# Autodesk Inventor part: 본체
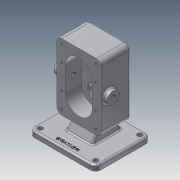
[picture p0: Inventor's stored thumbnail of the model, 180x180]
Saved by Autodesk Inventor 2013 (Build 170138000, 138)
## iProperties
Created: 2020-04
Part Number: 본체
Material: 알루미늄 6061
Document SubType Name: Modeling
Designer: CADCOM
Density: 1 g/cm^3
Author: CADCOM
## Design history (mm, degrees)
sketch "스케치1"
  geometry: L1 (50, 60)-(-50, 60); L2 (-50, 60)-(-50, -60); L3 (-50, -60)-(50, -60); L4 (50, -60)-(50, 60); L5 (50, 60)-(-50, -60); L6 (-50, 60)-(50, -60); 1 further point
  constraints: 12 end point, 2 midpoint, 2 parallel, 1 horizontal, 1 perpendicular
  dimensions: "d0" = 100 distance of L3.end L2.end; "d1" = 120 distance of L2.end L1.end
extrude "돌출1" new body sketch "스케치1" distance "d2" = 10; taper "d3" = 0 deg
fillet "모깎기1" dims "d4" = 10
sketch "스케치2"
  geometry: A1 r 10 centre (-40, -50) between (-50, -50) and (-40, -60) reference; A2 r 10 centre (40, -50) between (40, -60) and (50, -50) reference; A3 r 10 centre (40, 50) between (50, 50) and (40, 60) reference; A4 r 10 centre (-40, 50) between (-40, 60) and (-50, 50) reference; 5 further points
  constraints: 4 coincident
hole "구멍1" sketch "스케치2" at (-40, 50), (40, 50), (40, -50), (-40, -50) diameter "d5" = 9; stored, may be unused: countersink angle "d9" = 90 deg, drill point angle "d11" = 118 deg; dims "d6" = 6, "d7" = 4, "d8" = 2, "d10" = 8
node "작업 평면1"
sketch "스케치3"
  geometry: L1 (20, -40)-(-33, -40); L2 (-33, -40)-(-33, 40); L3 (-33, 40)-(20, 40); L4 (20, 40)-(20, -40); L5 (-40, -60)-(40, -60) reference; L6 (40, 60)-(-40, 60) reference; L7 (-50, 50)-(-50, -50) reference; L8 (20, 0)-(-33, 0); 1 further point
  constraints: 10 end point, 2 midpoint, 2 parallel, 1 horizontal, 1 horizontal alignment, 1 perpendicular
  dimensions: "d13" = 53 distance of L2.end L3.end; "d14" = 80 distance of L1.end L2.end; "d15" = 70 distance between parallel lines of L7 L4
extrude "돌출2" join sketch "스케치3" distance "d16" = 120; taper "d17" = 0 deg
sketch "스케치4"
  geometry: L1 (50, 0)-(-50, 0) reference; L2 (-50, 0)-(-50, 10) reference; L3 (-50, 10)-(50, 10) reference; L4 (50, 10)-(50, 0) reference; L5 (-20, 30)-(-20, 150) reference; L6 (-20, 150)-(33, 150) reference; L7 (33, 150)-(33, 30) reference; L8 (33, 30)-(-20, 30) reference; L9 (21.453, 30)-(33, 10); L10 (-8.453, 30)-(-20, 10); L11 (-8.453, 30)-(21.453, 30); L12 (33, 10)-(-20, 10); 1 further point
  constraints: 8 end point, 4 point on line, 2 collinear
  dimensions: "d18" = 17 distance of L3.end L9.end; "d19" = 60 deg angle of L3 L9; "d20" = 53 distance of L9.end L10.end; "d21" = 60 deg angle of L3 L10
extrude "돌출3" join sketch "스케치4" stored distance "d22" = 48; taper "d23" = 0 deg
fillet "모깎기2" dims "d24" = 9
sketch "스케치5"
  geometry: A1 r 9 centre (0, 9) between (-9, 9) and (0, 0) reference; A2 r 9 centre (62, 9) between (62, 0) and (71, 9) reference; A3 r 9 centre (62, 111) between (71, 111) and (62, 120) reference; A4 r 9 centre (0, 111) between (0, 120) and (-9, 111) reference; 9 further points
  constraints: 4 coincident, 4 vertical alignment, 2 horizontal alignment
  dimensions: "d25" = 29 distance of point (0, 82) point (0, 111); "d27" = 44 distance of point (0, 38) point (0, 82)
hole "구멍2" sketch "스케치5" at (0, 111), (62, 111), (62, 9), (0, 9), (0, 38), (62, 38), (62, 82), (0, 82) diameter "d28" = 4.134; stored, may be unused: countersink angle "d32" = 90 deg, drill point angle "d34" = 118 deg; dims "d29" = 10, "d30" = 4, "d31" = 2, "d33" = 12
sketch "스케치6"
  geometry: L1 (62, 0)-(0, 0) reference; L2 (0, 120)-(62, 120) reference; L3 (-9, 9)-(-9, 111) reference; L4 (7, 82)-(7, 38); L5 (55, 82)-(55, 38); L6 (7, 60)-(55, 60); A1 r 24 centre (31, 38) between (7, 38) and (55, 38); A2 r 24 centre (31, 82) between (55, 82) and (7, 82); 5 further points
  constraints: 6 end point, 6 point on circle, 4 midpoint, 2 centre point, 2 tangent, 2 vertical alignment, 1 parallel
  dimensions: "d36" = 24 radius of A1; "d37" = 92 distance of point (31, 14) point (31, 106); "d38" = 22 distance from line of A2.centre L6; "d39" = 14 distance from line of point (31, 106) L2; "d40" = 24 radius of A2
extrude "돌출4" cut sketch "스케치6" distance "d41" = 29; taper "d42" = 0 deg
sketch "스케치7"
  geometry: C1 r 12.5 at (31, 82); A1 r 24 centre (31, 82) between (55, 82) and (7, 82) reference; 1 further point
  constraints: 1 centre point, 1 coincident
  dimensions: "d43" = 25 diameter of C1
extrude "돌출5" cut sketch "스케치7" distance "d44" = 15; taper "d45" = 0 deg
sketch "스케치9"
  geometry: C1 r 12.5 at (31, 38); A1 r 24 centre (31, 38) between (7, 38) and (55, 38) reference; 1 further point
  constraints: 1 centre point, 1 coincident
  dimensions: "d49" = 25 diameter of C1
extrude "돌출7" cut sketch "스케치9" distance "d50" = 15; taper "d51" = 0 deg
sketch "스케치10"
  geometry: L1 (0, 0)-(0, 102) reference; L2 (0, 0)-(0, 102) reference; L3 (0, 102)-(53, 102) reference; L4 (53, 102)-(53, 0) reference; L5 (53, 0)-(0, 0) reference; L6 (70, -39)-(-30, -39) reference; L7 (-30, -39)-(-30, -29) reference; L8 (-30, -29)-(70, -29) reference; L9 (70, -29)-(70, -39) reference; C1 r 11 at (14, 51); 1 further point
  constraints: 1 centre point
  dimensions: "d52" = 22 diameter of C1; "d53" = 14 distance from line of C1.centre L1; "d106" = 90 distance from line of L6 C1.centre
extrude "돌출8" join sketch "스케치10" distance "d54" = 8; taper "d55" = 0 deg
sketch "스케치13"
  geometry: C1 r 11 at (0, 0) reference; 2 further points
  constraints: 1 coincident
hole "구멍5" sketch "스케치13" at (0, 0) diameter "d70" = 8.376; stored, may be unused: countersink angle "d74" = 90 deg, drill point angle "d76" = 118 deg; dims "d71" = 30, "d72" = 4, "d73" = 2, "d75" = 30
sketch "스케치14"
  geometry: C1 r 8.5 at (31, 82) reference; C2 r 19 at (31, 82); 1 further point
  constraints: 1 centre point, 1 coincident
  dimensions: "d77" = 38 diameter of C2
extrude "돌출9" join sketch "스케치14" distance "d78" = 17; taper "d79" = 0 deg
sketch "스케치15"
  geometry: C1 r 19 at (0, 0) reference; C2 r 14 at (0, 0); 1 further point
  constraints: 1 centre point, 1 coincident
  dimensions: "d80" = 28 diameter of C2
extrude "돌출10" cut sketch "스케치15" distance "d81" = 7.3; taper "d82" = 0 deg
sketch "스케치16"
  geometry: C1 r 12.5 at (0, 0) reference; C2 r 8.5 at (0, 0); 1 further point
  constraints: 1 centre point, 1 coincident
  dimensions: "d83" = 17 diameter of C2
extrude "돌출11" cut sketch "스케치16" stored distance "d84" = 7.3; taper "d85" = 0 deg
chamfer "모따기1" distance "d86" = 0.7; stored, may be unused: second distance "d87" = 2, angle "d88" = 30 deg
fillet "모깎기3" dims "d89" = 0.5
fillet "모깎기4" dims "d90" = 3
fillet "모깎기5" dims "d91" = 3
fillet "모깎기6" dims "d92" = 3
fillet "모깎기7" dims "d93" = 3
fillet "모깎기8" dims "d94" = 3
chamfer "모따기2" distance "d95" = 1; stored, may be unused: second distance "d96" = 2, angle "d97" = 30 deg
chamfer "모따기3" distance "d98" = 1; stored, may be unused: second distance "d99" = 2, angle "d100" = 30 deg
sketch "스케치17"
  geometry: L1 (40, 60)-(-40, 60) reference; L2 (-50, 50)-(-50, -50) reference; 2 further points
  constraints: 1 other
  dimensions: "d102" = 10 distance from line of L2 point (-40, 0); "d103" = 60 distance from line of L1 point (-40, 0)
feature "엠보싱1" sketch "스케치17" dims "d0" = 100, "d1" = 120, "d104" = 0.5, "d105" = 0
node "솔리드1"
mirror "대칭1"
mirror "대칭2"
node "절단 모서리 투영1"
node "절단 모서리 투영2"
other parameters: "d35" = 24
